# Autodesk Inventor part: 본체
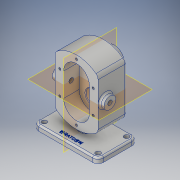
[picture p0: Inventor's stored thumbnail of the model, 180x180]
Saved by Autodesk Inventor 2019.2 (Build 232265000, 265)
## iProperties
Created: 2019-03
Part Number: 본체
Material: 알루미늄 6061
Document SubType Name: Modeling
Designer: User
Density: 2.7 g/cm^3
Appearance: 알루미늄 - 평지
Mass: 1187.16 g
Surface Area: 719.273 cm^2
Volume: 439.69 cm^3
Author: User
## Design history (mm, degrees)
sketch "스케치4"
  geometry: L1 (0, 87.6)-(0, -105.6) reference; L2 (-84, 0)-(84, 0) reference; L3 (40, 44.721)-(40, -44.721); L4 (-40, 44.721)-(-40, -44.721); A1 r 60 centre (0, 0) between (-40, -44.721) and (40, -44.721); A2 r 60 centre (0, 0) between (40, 44.721) and (-40, 44.721); 2 further points
  constraints: 4 end point, 4 point on circle, 2 centre point, 1 symmetric about line, 1 vertical
  dimensions: "d30" = 0 distance from line of L1 A1.centre; "d31" = 0 distance from line of L2 A1.centre; "d33" = 40 distance between parallel lines of L1 L4; "d34" = 80 distance between parallel lines of L3 L4; "d35" = 60 radius of A2; "d36" = 60 radius of A1
extrude "돌출1" new body sketch "스케치4" distance "d22" = 53; taper "d23" = 0 deg
sketch "스케치5"
  geometry: L1 (-60, -68)-(60, -68); L2 (60, -68)-(60, -78); L3 (60, -78)-(-60, -78); L4 (-60, -78)-(-60, -68); L5 (0, 87.6)-(0, -105.6) reference; L6 (-84, 0)-(84, 0) reference; 1 further point
  constraints: 8 end point, 2 parallel, 1 horizontal, 1 perpendicular
  dimensions: "d24" = 10 distance of L1.end L2.end; "d25" = 120 distance of L2.end L3.end; "d26" = 60 distance between parallel lines of L5 L2; "d27" = 78 distance between parallel lines of L6 L3
extrude "돌출2" join sketch "스케치5" distance "d37" = 20; taper "d39" = 0 deg; dims "d38" = 53, "d40" = 0
sketch "스케치6"
  geometry: L1 (0, -105.6)-(0, 87.6) reference; L2 (-84, 0)-(84, 0) reference; C1 r 19 at (0, 22); 1 further point
  constraints: 1 centre point
  dimensions: "d41" = 0 distance from line of L1 C1.centre; "d42" = 22 distance from line of L2 C1.centre; "d125" = 38 diameter of C1
extrude "돌출3" join sketch "스케치6" distance "d43" = 17; taper "d44" = 0 deg
sketch "스케치7"
  geometry: L1 (-38, 44.721)-(88, 44.721) reference; L2 (-20, -33.279)-(-20, -23.279) reference; L3 (0, 0)-(0, 89.443) reference; C1 r 11 at (14, 44.721); 1 further point
  constraints: 1 centre point
  dimensions: "d45" = 0 distance from line of L1 C1.centre; "d46" = 22 diameter of C1; "d124" = 14 distance from line of C1.centre L3
extrude "돌출4" join sketch "스케치7" distance "d48" = 8; taper "d49" = 0 deg
sketch "스케치8"
  geometry: L1 (-68, -53)-(-68, 20) reference; L2 (-68, -10)-(-55.776, -10); L3 (-55.776, -10)-(-55.776, -53); L4 (-55.776, -53)-(-68, -53); L5 (-68, -53)-(-68, -10); L6 (-105.6, 0)-(87.6, 0) reference; 1 further point
  constraints: 8 end point, 2 parallel, 1 horizontal, 1 perpendicular, 1 point on line
  dimensions: "d50" = 43 distance of L2.end L3.end; "d51" = 12.2244 distance of L3.end L4.end; "d52" = 10 distance between parallel lines of L6 L2
extrude "돌출5" join sketch "스케치8" stored distance "d53" = 12; taper "d54" = 0 deg
sketch "스케치9"
  geometry: L1 (0, 87.6)-(0, -105.6) reference; L2 (-84, 0)-(84, 0) reference; L3 (24, 22)-(24, -22); L4 (-24, 22)-(-24, -22); A1 r 24 centre (0, 22) between (24, 22) and (-24, 22); A2 r 24 centre (0, -22) between (-24, -22) and (24, -22); 1 further point
  constraints: 4 end point, 4 point on circle, 2 centre point, 2 tangent, 2 vertical
  dimensions: "d55" = 48 diameter of A1; "d56" = 48 diameter of A2; "d57" = 0 distance from line of L1 A1.centre; "d58" = 0 distance from line of L1 A2.centre; "d59" = 22 distance from line of L2 A1.centre; "d60" = 44 distance of A1.centre A2.centre
extrude "돌출6" cut sketch "스케치9" distance "d61" = 29; taper "d62" = 0 deg
sketch "스케치10"
  geometry: L1 (0, 87.6)-(0, -105.6) reference; L2 (-84, 0)-(84, 0) reference; C1 r 12.5 at (0, 22); C2 r 12.5 at (0, -22); 1 further point
  constraints: 2 centre point
  dimensions: "d63" = 25 diameter of C2; "d64" = 25 diameter of C1; "d65" = 0 distance from line of L1 C1.centre; "d66" = 0 distance from line of L1 C2.centre; "d67" = 44 distance of C1.centre C2.centre; "d68" = 22 distance from line of L2 C1.centre
extrude "돌출7" cut sketch "스케치10" distance "d69" = 15; taper "d70" = 0 deg
sketch "스케치11"
  geometry: C1 r 19 at (0, 0) reference; 2 further points
  constraints: 1 coincident
hole "구멍1" sketch "스케치11" at (0, 0) diameter "d71" = 17; stored, may be unused: countersink angle "d75" = 90 deg, drill point angle "d77" = 0 deg; dims "d72" = 8, "d73" = 28, "d74" = 7.3, "d76" = 30
sketch "스케치12"
  geometry: C1 r 11 at (0, 0) reference; 2 further points
  constraints: 1 coincident
hole "구멍2" sketch "스케치12" at (0, 0) diameter "d78" = 8.376; stored, may be unused: countersink angle "d82" = 90 deg, drill point angle "d84" = 118 deg; dims "d79" = 200, "d80" = 28, "d81" = 7.3, "d83" = 27.3
fillet "모깎기1" dims "d85" = 10
sketch "스케치13"
  geometry: L1 (-84, 0)-(84, 0) reference; C1 r 12.5 at (0, 22) reference; A1 r 31 centre (0, 22) between (-31, 22) and (31, 22); 2 further points
  constraints: 2 point on circle, 1 centre point, 1 coincident
  dimensions: "d93" = 62 diameter of A1; "d94" = 0 horizontal distance of A1.centre point (0, 53); "d95" = 31 distance of A1.centre point (0, 53); "d96" = 22 distance from line of L1 A1.end; "d97" = 22 distance from line of L1 A1.start
hole "구멍3" sketch "스케치13" at (0, 53), (31, 22), (-31, 22) diameter "d86" = 4.134; stored, may be unused: countersink angle "d90" = 90 deg, drill point angle "d92" = 118 deg; dims "d87" = 10, "d88" = 28, "d89" = 7.3, "d91" = 12
sketch "스케치15"
  geometry: A1 r 10 centre (-44, -20) between (-54, -20) and (-44, -30) reference; A2 r 10 centre (56, -20) between (56, -30) and (66, -20) reference; A3 r 10 centre (56, 33) between (66, 33) and (56, 43) reference; A4 r 10 centre (-44, 33) between (-44, 43) and (-54, 33) reference; 5 further points
  constraints: 4 coincident
hole "구멍4" sketch "스케치15" at (-44, -20), (56, -20), (56, 33), (-44, 33) diameter "d98" = 9; stored, may be unused: countersink angle "d102" = 90 deg, drill point angle "d104" = 118 deg; dims "d99" = 10, "d100" = 28, "d101" = 7.3, "d103" = 12
fillet "모깎기2" dims "d105" = 3
fillet "모깎기3" dims "d106" = 3
fillet "모깎기4" dims "d107" = 10
fillet "모깎기5" dims "d108" = 3
fillet "모깎기7" dims "d110" = 3
chamfer "모따기1" distance "d113" = 1; stored, may be unused: second distance "d114" = 2, angle "d115" = 45 deg
fillet "모깎기10" dims "d116" = 0.5
chamfer "모따기2" distance "d117" = 0.7; stored, may be unused: second distance "d118" = 2, angle "d119" = 30 deg
sketch "스케치17"
  geometry: L1 (53, -27)-(-47, -27) reference; L2 (-57, 36)-(-57, -17) reference; 2 further points
  constraints: 1 other
  dimensions: "d128" = 10 distance from line of L1 point (3, -17); "d129" = 60 distance from line of point (3, -17) L2
feature "엠보싱1" sketch "스케치17" dims "d122" = 0.5, "d123" = 0
fillet "모깎기11" dims "d126" = 3
fillet "모깎기12" dims "d127" = 3
node "솔리드1"
mirror "미러1"
mirror "미러2"
